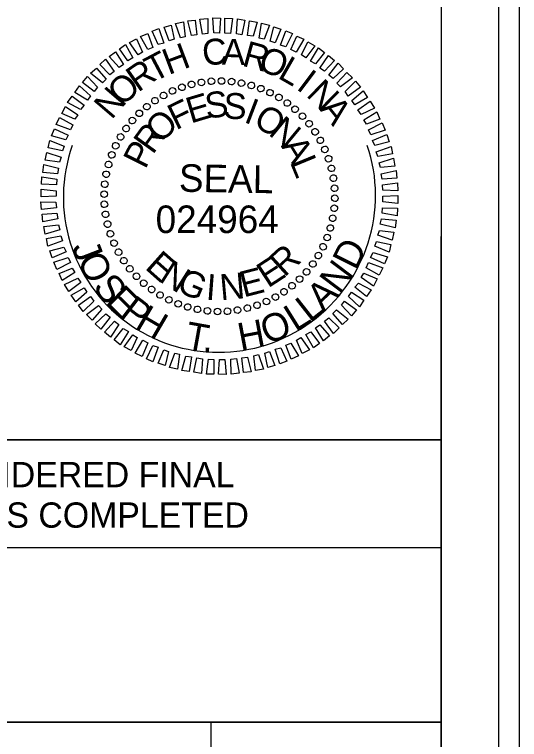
# Model space of a CAD drawing. Extents: x 1640342 to 1730599, y 538663 to 843747.
# Drawn here: x 1730155.44 to 1730177.39, y 539559.08 to 539590.64 of the extents above; entities that cross this region are included whole.
import ezdxf

# ---------------------------------------------------------------- set-up
doc = ezdxf.new("R2010")
doc.units = 0
for name, color, linetype in [('Sheet Clip Boundary CELL', 7, 'Continuous'), ('Sheet Layout Plan Border', 7, 'Continuous'), ('Sheet PE Seal Cell', 7, 'Continuous'), ('Sheet Plan CELL', 7, 'Continuous'), ('Sheet Plan Layout CELL', 7, 'Continuous'), ('Sheet Plot Border Inside CELL', 7, 'Continuous'), ('Sheet Plot Border Outside CELL', 7, 'Continuous'), ('Sheet Sticker Exception Certification CELL', 7, 'Continuous')]:
    doc.layers.add(name, color=color, linetype=linetype)

msp = doc.modelspace()

# ---------------------------------------------------------------- linework, layer by layer
at = {"layer": 'Sheet Clip Boundary CELL'}
msp.add_lwpolyline([(1729883.99, 539392.14), (1730163.993, 539392.14), (1730163.993, 539559.842), (1730126.14, 539559.842), (1730126.14, 539602.14), (1729883.99, 539602.14)], close=True, dxfattribs=at)
at = {"layer": 'Sheet Layout Plan Border'}
msp.add_lwpolyline([(1729883.99, 539392.14), (1730163.993, 539392.14), (1730163.993, 539559.842), (1730126.14, 539559.842), (1730126.14, 539602.14), (1729883.99, 539602.14)], close=True, dxfattribs=at)
at = {"layer": 'Sheet PE Seal Cell'}
for p, q in [((1730163.569, 539587.676), (1730163.569, 539587.676)), ((1730163.999, 539587.736), (1730163.999, 539587.736)), ((1730164.439, 539587.746), (1730164.439, 539587.746)), ((1730164.879, 539587.716), (1730164.879, 539587.716)), ((1730165.309, 539587.646), (1730165.309, 539587.646)), ((1730162.309, 539587.316), (1730162.309, 539587.316)), ((1730162.709, 539587.476), (1730162.709, 539587.476)), ((1730163.129, 539587.596), (1730163.129, 539587.596)), ((1730165.729, 539587.556), (1730165.729, 539587.556)), ((1730166.149, 539587.416), (1730166.149, 539587.416)), ((1730161.919, 539587.116), (1730161.919, 539587.116)), ((1730166.549, 539587.236), (1730166.549, 539587.236)), ((1730166.939, 539587.036), (1730166.939, 539587.036)), ((1730161.539, 539586.886), (1730161.539, 539586.886)), ((1730167.299, 539586.786), (1730167.299, 539586.786)), ((1730161.189, 539586.636), (1730161.189, 539586.636)), ((1730167.649, 539586.516), (1730167.649, 539586.516)), ((1730160.859, 539586.336), (1730160.859, 539586.336)), ((1730167.959, 539586.216), (1730167.959, 539586.216)), ((1730160.559, 539586.026), (1730160.559, 539586.026)), ((1730168.259, 539585.886), (1730168.259, 539585.886)), ((1730160.289, 539585.676), (1730160.289, 539585.676)), ((1730168.509, 539585.536), (1730168.509, 539585.536)), ((1730160.039, 539585.316), (1730160.039, 539585.316)), ((1730168.739, 539585.156), (1730168.739, 539585.156)), ((1730159.839, 539584.926), (1730159.839, 539584.926)), ((1730159.659, 539584.526), (1730159.659, 539584.526)), ((1730168.939, 539584.766), (1730168.939, 539584.766)), ((1730169.099, 539584.366), (1730169.099, 539584.366)), ((1730159.519, 539584.106), (1730159.519, 539584.106)), ((1730169.219, 539583.946), (1730169.219, 539583.946)), ((1730159.429, 539583.686), (1730159.429, 539583.686)), ((1730159.359, 539583.256), (1730159.359, 539583.256)), ((1730169.299, 539583.506), (1730169.299, 539583.506)), ((1730169.359, 539583.076), (1730169.359, 539583.076)), ((1730159.329, 539582.816), (1730159.329, 539582.816)), ((1730169.369, 539582.636), (1730169.369, 539582.636)), ((1730159.339, 539582.376), (1730159.339, 539582.376)), ((1730159.399, 539581.946), (1730159.399, 539581.946)), ((1730169.339, 539582.196), (1730169.339, 539582.196)), ((1730169.269, 539581.766), (1730169.269, 539581.766)), ((1730159.479, 539581.506), (1730159.479, 539581.506)), ((1730169.179, 539581.346), (1730169.179, 539581.346)), ((1730159.599, 539581.086), (1730159.599, 539581.086)), ((1730159.759, 539580.686), (1730159.759, 539580.686)), ((1730169.039, 539580.926), (1730169.039, 539580.926)), ((1730168.859, 539580.526), (1730168.859, 539580.526)), ((1730159.959, 539580.296), (1730159.959, 539580.296)), ((1730168.659, 539580.136), (1730168.659, 539580.136)), ((1730160.189, 539579.916), (1730160.189, 539579.916)), ((1730168.409, 539579.776), (1730168.409, 539579.776)), ((1730160.439, 539579.566), (1730160.439, 539579.566)), ((1730168.139, 539579.426), (1730168.139, 539579.426)), ((1730160.739, 539579.236), (1730160.739, 539579.236)), ((1730167.839, 539579.116), (1730167.839, 539579.116)), ((1730161.049, 539578.936), (1730161.049, 539578.936)), ((1730167.509, 539578.816), (1730167.509, 539578.816)), ((1730161.399, 539578.666), (1730161.399, 539578.666)), ((1730167.159, 539578.566), (1730167.159, 539578.566)), ((1730161.759, 539578.416), (1730161.759, 539578.416)), ((1730162.149, 539578.216), (1730162.149, 539578.216)), ((1730166.779, 539578.336), (1730166.779, 539578.336)), ((1730162.549, 539578.036), (1730162.549, 539578.036)), ((1730162.969, 539577.896), (1730162.969, 539577.896)), ((1730165.569, 539577.856), (1730165.569, 539577.856)), ((1730165.989, 539577.976), (1730165.989, 539577.976)), ((1730166.389, 539578.136), (1730166.389, 539578.136)), ((1730163.389, 539577.806), (1730163.389, 539577.806)), ((1730163.819, 539577.736), (1730163.819, 539577.736)), ((1730164.259, 539577.706), (1730164.259, 539577.706)), ((1730164.699, 539577.716), (1730164.699, 539577.716)), ((1730165.129, 539577.776), (1730165.129, 539577.776))]:
    msp.add_line(p, q, dxfattribs=at)
for points in [[(1730163.609, 539589.786), (1730163.499, 539590.426), (1730163.839, 539590.466), (1730163.849, 539589.816)], [(1730164.109, 539589.836), (1730164.059, 539590.486), (1730164.389, 539590.476), (1730164.349, 539589.826)], [(1730164.589, 539589.826), (1730164.589, 539590.476), (1730164.919, 539590.466), (1730164.829, 539589.816)], [(1730162.169, 539589.486), (1730161.939, 539590.086), (1730162.249, 539590.176), (1730162.379, 539589.556)], [(1730162.649, 539589.616), (1730162.439, 539590.246), (1730162.779, 539590.316), (1730162.859, 539589.666)], [(1730163.129, 539589.726), (1730162.969, 539590.366), (1730163.299, 539590.396), (1730163.369, 539589.756)], [(1730165.089, 539589.796), (1730165.129, 539590.446), (1730165.459, 539590.386), (1730165.329, 539589.756)], [(1730165.569, 539589.716), (1730165.659, 539590.356), (1730165.989, 539590.306), (1730165.809, 539589.686)], [(1730166.079, 539589.606), (1730166.179, 539590.256), (1730166.519, 539590.176), (1730166.289, 539589.556)], [(1730161.679, 539589.326), (1730161.419, 539589.906), (1730161.719, 539590.026), (1730161.929, 539589.386)], [(1730166.559, 539589.476), (1730166.709, 539590.096), (1730167.019, 539589.996), (1730166.769, 539589.406)], [(1730167.009, 539589.296), (1730167.239, 539589.926), (1730167.519, 539589.806), (1730167.239, 539589.226)], [(1730160.809, 539588.876), (1730160.439, 539589.416), (1730160.749, 539589.576), (1730160.999, 539588.996)], [(1730161.239, 539589.116), (1730160.919, 539589.676), (1730161.229, 539589.816), (1730161.459, 539589.206)], [(1730167.459, 539589.106), (1730167.709, 539589.696), (1730168.019, 539589.556), (1730167.679, 539588.996)], [(1730160.369, 539588.626), (1730159.999, 539589.136), (1730160.259, 539589.326), (1730160.589, 539588.746)], [(1730167.919, 539588.876), (1730168.189, 539589.446), (1730168.489, 539589.276), (1730168.109, 539588.756)], [(1730159.989, 539588.326), (1730159.559, 539588.806), (1730159.829, 539589.016), (1730160.179, 539588.456)], [(1730168.309, 539588.606), (1730168.659, 539589.186), (1730168.919, 539588.976), (1730168.529, 539588.486)], [(1730159.589, 539588.016), (1730159.149, 539588.456), (1730159.389, 539588.696), (1730159.779, 539588.156)], [(1730168.719, 539588.306), (1730169.089, 539588.856), (1730169.349, 539588.636), (1730168.909, 539588.166)], [(1730159.259, 539587.666), (1730158.749, 539588.076), (1730158.999, 539588.306), (1730159.419, 539587.826)], [(1730169.099, 539587.996), (1730169.509, 539588.516), (1730169.749, 539588.276), (1730169.289, 539587.846)], [(1730158.909, 539587.286), (1730158.389, 539587.676), (1730158.609, 539587.936), (1730159.049, 539587.466)], [(1730169.459, 539587.646), (1730169.889, 539588.116), (1730170.129, 539587.876), (1730169.609, 539587.486)], [(1730169.809, 539587.286), (1730170.269, 539587.736), (1730170.479, 539587.466), (1730169.949, 539587.086)], [(1730158.609, 539586.906), (1730158.069, 539587.246), (1730158.259, 539587.536), (1730158.739, 539587.096)], [(1730170.109, 539586.896), (1730170.599, 539587.316), (1730170.789, 539587.026), (1730170.229, 539586.706)], [(1730158.309, 539586.506), (1730157.749, 539586.806), (1730157.949, 539587.086), (1730158.469, 539586.686)], [(1730170.369, 539586.486), (1730170.899, 539586.866), (1730171.089, 539586.566), (1730170.509, 539586.286)], [(1730158.069, 539586.076), (1730157.499, 539586.326), (1730157.649, 539586.636), (1730158.189, 539586.266)], [(1730170.629, 539586.046), (1730171.189, 539586.396), (1730171.319, 539586.086), (1730170.749, 539585.856)], [(1730157.869, 539585.616), (1730157.249, 539585.846), (1730157.399, 539586.156), (1730157.969, 539585.836)], [(1730170.829, 539585.616), (1730171.419, 539585.916), (1730171.549, 539585.596), (1730170.929, 539585.396)], [(1730157.669, 539585.176), (1730157.049, 539585.356), (1730157.179, 539585.666), (1730157.779, 539585.386)], [(1730157.519, 539584.696), (1730156.899, 539584.826), (1730156.969, 539585.156), (1730157.599, 539584.906)], [(1730171.009, 539585.146), (1730171.619, 539585.406), (1730171.729, 539585.096), (1730171.109, 539584.936)], [(1730171.169, 539584.666), (1730171.809, 539584.896), (1730171.869, 539584.566), (1730171.239, 539584.456)], [(1730157.389, 539584.216), (1730156.769, 539584.296), (1730156.839, 539584.636), (1730157.469, 539584.426)], [(1730171.289, 539584.186), (1730171.919, 539584.376), (1730171.979, 539584.036), (1730171.349, 539583.976)], [(1730157.309, 539583.706), (1730156.669, 539583.766), (1730156.709, 539584.106), (1730157.359, 539583.946)], [(1730171.379, 539583.706), (1730172.029, 539583.846), (1730172.059, 539583.506), (1730171.419, 539583.466)], [(1730157.259, 539583.226), (1730156.609, 539583.246), (1730156.629, 539583.576), (1730157.279, 539583.466)], [(1730171.439, 539583.226), (1730172.089, 539583.306), (1730172.109, 539582.966), (1730171.459, 539582.986)], [(1730157.249, 539582.726), (1730156.599, 539582.696), (1730156.599, 539583.036), (1730157.249, 539582.966)], [(1730171.449, 539582.726), (1730172.099, 539582.756), (1730172.099, 539582.416), (1730171.449, 539582.486)], [(1730157.259, 539582.226), (1730156.609, 539582.146), (1730156.589, 539582.486), (1730157.239, 539582.466)], [(1730157.319, 539581.746), (1730156.669, 539581.606), (1730156.639, 539581.946), (1730157.279, 539581.986)], [(1730171.439, 539582.226), (1730172.089, 539582.206), (1730172.069, 539581.876), (1730171.419, 539581.986)], [(1730171.389, 539581.746), (1730172.029, 539581.686), (1730171.989, 539581.346), (1730171.339, 539581.506)], [(1730157.409, 539581.266), (1730156.779, 539581.076), (1730156.719, 539581.416), (1730157.349, 539581.476)], [(1730157.529, 539580.786), (1730156.889, 539580.556), (1730156.829, 539580.886), (1730157.459, 539580.996)], [(1730171.309, 539581.236), (1730171.929, 539581.156), (1730171.859, 539580.816), (1730171.229, 539581.026)], [(1730171.179, 539580.756), (1730171.799, 539580.626), (1730171.729, 539580.296), (1730171.099, 539580.546)], [(1730157.689, 539580.306), (1730157.079, 539580.046), (1730156.969, 539580.356), (1730157.589, 539580.516)], [(1730157.869, 539579.836), (1730157.279, 539579.536), (1730157.149, 539579.856), (1730157.769, 539580.056)], [(1730171.029, 539580.276), (1730171.649, 539580.096), (1730171.519, 539579.786), (1730170.919, 539580.066)], [(1730170.829, 539579.836), (1730171.449, 539579.606), (1730171.299, 539579.296), (1730170.729, 539579.616)], [(1730158.069, 539579.406), (1730157.509, 539579.056), (1730157.379, 539579.366), (1730157.949, 539579.596)], [(1730158.329, 539578.966), (1730157.799, 539578.586), (1730157.609, 539578.886), (1730158.189, 539579.166)], [(1730170.629, 539579.376), (1730171.199, 539579.126), (1730171.049, 539578.816), (1730170.509, 539579.186)], [(1730170.389, 539578.946), (1730170.949, 539578.646), (1730170.749, 539578.366), (1730170.229, 539578.766)], [(1730158.589, 539578.556), (1730158.099, 539578.136), (1730157.909, 539578.426), (1730158.469, 539578.746)], [(1730170.089, 539578.546), (1730170.629, 539578.206), (1730170.439, 539577.916), (1730169.959, 539578.356)], [(1730158.889, 539578.166), (1730158.429, 539577.716), (1730158.219, 539577.986), (1730158.749, 539578.366)], [(1730169.789, 539578.166), (1730170.309, 539577.776), (1730170.089, 539577.516), (1730169.649, 539577.986)], [(1730159.239, 539577.806), (1730158.809, 539577.336), (1730158.569, 539577.576), (1730159.089, 539577.966)], [(1730159.599, 539577.456), (1730159.189, 539576.936), (1730158.949, 539577.176), (1730159.409, 539577.606)], [(1730169.439, 539577.786), (1730169.949, 539577.376), (1730169.699, 539577.146), (1730169.279, 539577.626)], [(1730159.979, 539577.146), (1730159.609, 539576.596), (1730159.349, 539576.816), (1730159.789, 539577.286)], [(1730169.109, 539577.436), (1730169.549, 539576.996), (1730169.309, 539576.756), (1730168.919, 539577.296)], [(1730160.389, 539576.846), (1730160.039, 539576.266), (1730159.779, 539576.476), (1730160.169, 539576.966)], [(1730168.709, 539577.126), (1730169.139, 539576.646), (1730168.869, 539576.436), (1730168.519, 539576.996)], [(1730160.779, 539576.576), (1730160.509, 539576.006), (1730160.209, 539576.176), (1730160.589, 539576.696)], [(1730167.889, 539576.576), (1730168.259, 539576.036), (1730167.949, 539575.876), (1730167.699, 539576.456)], [(1730168.329, 539576.826), (1730168.699, 539576.316), (1730168.439, 539576.126), (1730168.109, 539576.706)], [(1730161.239, 539576.346), (1730160.989, 539575.756), (1730160.679, 539575.896), (1730161.019, 539576.456)], [(1730167.459, 539576.336), (1730167.779, 539575.776), (1730167.469, 539575.636), (1730167.239, 539576.246)], [(1730161.689, 539576.156), (1730161.459, 539575.526), (1730161.179, 539575.646), (1730161.459, 539576.226)], [(1730162.139, 539575.976), (1730161.989, 539575.356), (1730161.679, 539575.456), (1730161.929, 539576.046)], [(1730166.529, 539575.966), (1730166.759, 539575.366), (1730166.449, 539575.276), (1730166.319, 539575.896)], [(1730167.019, 539576.126), (1730167.279, 539575.546), (1730166.979, 539575.426), (1730166.769, 539576.066)], [(1730162.619, 539575.846), (1730162.519, 539575.196), (1730162.179, 539575.276), (1730162.409, 539575.896)], [(1730163.129, 539575.736), (1730163.039, 539575.096), (1730162.709, 539575.146), (1730162.889, 539575.766)], [(1730163.609, 539575.656), (1730163.569, 539575.006), (1730163.239, 539575.066), (1730163.369, 539575.696)], [(1730164.109, 539575.626), (1730164.109, 539574.976), (1730163.779, 539574.986), (1730163.869, 539575.636)], [(1730164.589, 539575.616), (1730164.639, 539574.966), (1730164.309, 539574.976), (1730164.349, 539575.626)], [(1730165.089, 539575.666), (1730165.199, 539575.026), (1730164.859, 539574.986), (1730164.849, 539575.636)], [(1730165.569, 539575.726), (1730165.729, 539575.086), (1730165.399, 539575.056), (1730165.329, 539575.696)], [(1730166.049, 539575.836), (1730166.259, 539575.206), (1730165.919, 539575.136), (1730165.839, 539575.786)]]:
    msp.add_lwpolyline(points, close=True, dxfattribs=at)
for centre, major_axis in [((1730162.716, 539587.469), (-0.047, 0.136)), ((1730163.136, 539587.593), (-0.035, 0.14)), ((1730163.565, 539587.68), (-0.023, 0.142)), ((1730163.999, 539587.73), (-0.01, 0.144)), ((1730164.437, 539587.741), (0.003, 0.144)), ((1730164.874, 539587.715), (0.015, 0.143)), ((1730165.306, 539587.65), (0.027, 0.141)), ((1730165.732, 539587.548), (0.04, 0.138)), ((1730162.309, 539587.308), (-0.059, 0.132)), ((1730166.147, 539587.409), (0.052, 0.134)), ((1730166.548, 539587.234), (0.063, 0.129)), ((1730161.544, 539586.884), (-0.081, 0.119)), ((1730161.918, 539587.113), (-0.07, 0.126)), ((1730166.933, 539587.026), (0.074, 0.123)), ((1730161.193, 539586.624), (-0.091, 0.112)), ((1730167.298, 539586.784), (0.085, 0.116)), ((1730167.64, 539586.512), (0.094, 0.109)), ((1730160.865, 539586.334), (-0.1, 0.104)), ((1730167.958, 539586.21), (0.104, 0.1)), ((1730160.564, 539586.017), (-0.109, 0.094)), ((1730168.247, 539585.883), (0.112, 0.091)), ((1730160.291, 539585.674), (-0.116, 0.085)), ((1730160.05, 539585.309), (-0.123, 0.074)), ((1730168.508, 539585.531), (0.119, 0.081)), ((1730168.736, 539585.158), (0.126, 0.07)), ((1730159.841, 539584.925), (-0.129, 0.063)), ((1730168.932, 539584.766), (0.132, 0.059)), ((1730159.666, 539584.524), (-0.134, 0.052)), ((1730169.092, 539584.359), (0.136, 0.047)), ((1730159.528, 539584.109), (-0.138, 0.04)), ((1730159.425, 539583.683), (-0.141, 0.027)), ((1730169.216, 539583.939), (0.14, 0.035)), ((1730169.304, 539583.511), (0.142, 0.023)), ((1730159.361, 539583.25), (-0.143, 0.015)), ((1730169.353, 539583.076), (0.144, 0.01)), ((1730159.334, 539582.814), (-0.144, 0.003)), ((1730169.365, 539582.638), (0.144, -0.003)), ((1730159.346, 539582.376), (-0.144, -0.01)), ((1730169.338, 539582.202), (0.143, -0.015)), ((1730159.395, 539581.941), (-0.142, -0.023)), ((1730159.482, 539581.512), (-0.14, -0.035)), ((1730169.273, 539581.769), (0.141, -0.027)), ((1730169.171, 539581.343), (0.138, -0.04)), ((1730159.607, 539581.093), (-0.136, -0.047)), ((1730169.032, 539580.928), (0.134, -0.052)), ((1730159.767, 539580.686), (-0.132, -0.059)), ((1730168.858, 539580.527), (0.129, -0.063)), ((1730159.962, 539580.294), (-0.126, -0.07)), ((1730160.191, 539579.921), (-0.119, -0.081)), ((1730168.649, 539580.143), (0.123, -0.074)), ((1730160.451, 539579.569), (-0.112, -0.091)), ((1730168.407, 539579.778), (0.116, -0.085)), ((1730168.135, 539579.435), (0.109, -0.094)), ((1730160.741, 539579.242), (-0.104, -0.1)), ((1730161.059, 539578.94), (-0.094, -0.109)), ((1730167.834, 539579.118), (0.1, -0.104)), ((1730161.401, 539578.668), (-0.085, -0.116)), ((1730167.506, 539578.828), (0.091, -0.112)), ((1730161.766, 539578.426), (-0.074, -0.123)), ((1730166.781, 539578.339), (0.07, -0.126)), ((1730167.154, 539578.568), (0.081, -0.119)), ((1730162.15, 539578.218), (-0.063, -0.129)), ((1730162.552, 539578.043), (-0.052, -0.134)), ((1730166.39, 539578.144), (0.059, -0.132)), ((1730162.967, 539577.904), (-0.04, -0.138)), ((1730163.392, 539577.802), (-0.027, -0.141)), ((1730163.825, 539577.737), (-0.015, -0.143)), ((1730164.262, 539577.711), (-0.003, -0.144)), ((1730164.699, 539577.722), (0.01, -0.144)), ((1730165.134, 539577.772), (0.023, -0.142)), ((1730165.563, 539577.859), (0.035, -0.14)), ((1730165.982, 539577.983), (0.047, -0.136))]:
    msp.add_ellipse(centre, major_axis=major_axis, ratio=0.999708, dxfattribs=at)
at = {"layer": 'Sheet Plan CELL'}
for points in [[(1729873.99, 539392.14), (1729873.985, 539602.135), (1730133.983, 539602.142), (1730133.985, 539572.13), (1730173.993, 539572.127), (1730173.993, 539392.14)], [(1730173.998, 539602.14), (1729873.99, 539602.14), (1729873.99, 539392.14), (1730173.993, 539392.14)], [(1730153.993, 539594.627), (1730173.99, 539594.63), (1730173.993, 539572.127), (1730153.993, 539572.125)]]:
    msp.add_lwpolyline(points, close=True, dxfattribs=at)
at = {"layer": 'Sheet Plan Layout CELL'}
for points in [[(1729873.985, 539602.135), (1729873.99, 539392.14), (1730173.99, 539392.14), (1730173.99, 539559.842), (1730126.14, 539559.842), (1730126.14, 539602.14)], [(1730126.14, 539559.842), (1730173.995, 539559.842), (1730174, 539602.14), (1730126.14, 539602.14)]]:
    msp.add_lwpolyline(points, close=True, dxfattribs=at)
at = {"layer": 'Sheet Plot Border Inside CELL'}
msp.add_lwpolyline([(1729843.293, 539391.637), (1730176.49, 539391.64), (1730176.493, 539602.637), (1729843.293, 539602.637)], close=True, dxfattribs=at)
at = {"layer": 'Sheet Plot Border Outside CELL'}
msp.add_lwpolyline([(1729840.693, 539387.637), (1730177.393, 539387.637), (1730177.393, 539606.637), (1729840.693, 539606.637)], close=True, dxfattribs=at)
msp.add_ellipse((1730164.349, 539582.726), major_axis=(4.509, 5.104), ratio=0.993455, start_param=1.958957, end_param=5.764947, dxfattribs=at)
at = {"layer": 'Sheet Sticker Exception Certification CELL'}
for p, q in [((1730133.985, 539572.13), (1730173.993, 539572.13)), ((1730133.985, 539572.13), (1730173.993, 539572.13)), ((1730173.993, 539572.127), (1730173.993, 539567.427)), ((1730173.993, 539572.127), (1730173.993, 539567.427)), ((1730173.993, 539567.43), (1730133.985, 539567.43)), ((1730173.993, 539567.43), (1730133.985, 539567.43))]:
    msp.add_line(p, q, dxfattribs=at)

# ---------------------------------------------------------------- texts
at = {"layer": 'Sheet PE Seal Cell'}
for s, height, rotation, p in [('C', 1.128, 6.2199, (1730163.659, 539588.396)), ('A', 1.128, 359.0203, (1730164.449, 539588.456)), ('H', 1.128, 20.6195, (1730162.139, 539587.996)), ('R', 1.128, 344.6211, (1730165.289, 539588.416)), ('T', 1.128, 27.8198, (1730161.489, 539587.666)), ('O', 1.128, 337.4212, (1730165.959, 539588.266)), ('R', 1.128, 35.0205, (1730160.809, 539587.226)), ('L', 1.128, 330.2209, (1730166.839, 539587.896)), ('O', 1.128, 42.2217, (1730160.119, 539586.606)), ('I', 1.128, 323.0201, (1730167.649, 539587.416)), ('N', 1.128, 315.8189, (1730168.079, 539587.106)), ('N', 1.128, 49.4235, (1730159.659, 539586.026)), ('S', 1.128, 7.2556, (1730163.789, 539586.096)), ('E', 1.128, 16.6111, (1730163.099, 539585.886)), ('S', 1.128, 357.9004, (1730164.509, 539586.106)), ('F', 1.128, 25.967, (1730162.459, 539585.586)), ('I', 1.128, 339.1896, (1730165.369, 539585.966)), ('A', 1.128, 308.6172, (1730168.669, 539586.516)), ('O', 1.128, 44.6812, (1730161.799, 539584.996)), ('O', 1.128, 329.8335, (1730165.769, 539585.826)), ('N', 1.128, 320.4766, (1730166.439, 539585.426)), ('R', 1.128, 54.0397, (1730161.449, 539584.506)), ('P', 1.128, 63.3989, (1730161.129, 539583.866)), ('A', 1.128, 301.7603, (1730167.009, 539584.906)), ('L', 1.128, 292.4008, (1730167.399, 539584.216)), ('SEAL', 1.1996, 359, (1730162.579, 539582.926)), ('D', 1.2, 63.6039, (1730170.285, 539579.46)), ('J', 1.2, 291.2124, (1730157.911, 539580.52)), ('R', 1.128, 42.4814, (1730167.169, 539579.176)), ('O', 1.2, 296.4669, (1730158.135, 539579.943)), ('E', 1.128, 318.2769, (1730161.069, 539579.596)), ('E', 1.128, 33.1241, (1730166.459, 539578.706)), ('N', 1.128, 327.634, (1730161.669, 539579.056)), ('N', 1.2, 53.0513, (1730169.575, 539578.417)), ('G', 1.128, 336.9902, (1730162.429, 539578.606)), ('E', 1.128, 14.4118, (1730165.399, 539578.316)), ('S', 1.2, 308.0413, (1730158.806, 539578.761)), ('I', 1.128, 355.7012, (1730163.739, 539578.226)), ('N', 1.128, 5.0564, (1730164.409, 539578.196)), ('E', 1.2, 315.3853, (1730159.35, 539578.092)), ('A', 1.2, 44.3588, (1730168.854, 539577.668)), ('P', 1.2, 322.5143, (1730159.955, 539577.514)), ('L', 1.2, 38.1871, (1730168.277, 539577.206)), ('H', 1.2, 329.641, (1730160.627, 539577.016)), ('L', 1.2, 32.0108, (1730167.655, 539576.809)), ('O', 1.2, 20.6113, (1730166.41, 539576.262)), ('T', 1.2, 349.8271, (1730162.805, 539576.096)), ('H', 1.2, 10.7371, (1730165.267, 539575.997)), ('.', 1.2, 356.6032, (1730163.595, 539575.966))]:
    msp.add_text(s, height=height, rotation=rotation, dxfattribs=at).set_placement(p)
msp.add_text('024964', height=1.1996, dxfattribs=at).set_placement((1730161.574, 539581.124))
at = {"layer": 'Sheet Sticker Exception Certification CELL'}
for s, p in [('DOCUMENT NOT CONSIDERED FINAL', (1730138.199, 539570.061)), ('DOCUMENT NOT CONSIDERED FINAL', (1730138.199, 539570.061)), ('UNLESS ALL SIGNATURES COMPLETED', (1730137.185, 539568.301)), ('UNLESS ALL SIGNATURES COMPLETED', (1730137.185, 539568.301))]:
    msp.add_text(s, height=1.1, dxfattribs=at).set_placement(p)

doc.saveas('drawing.dxf')
